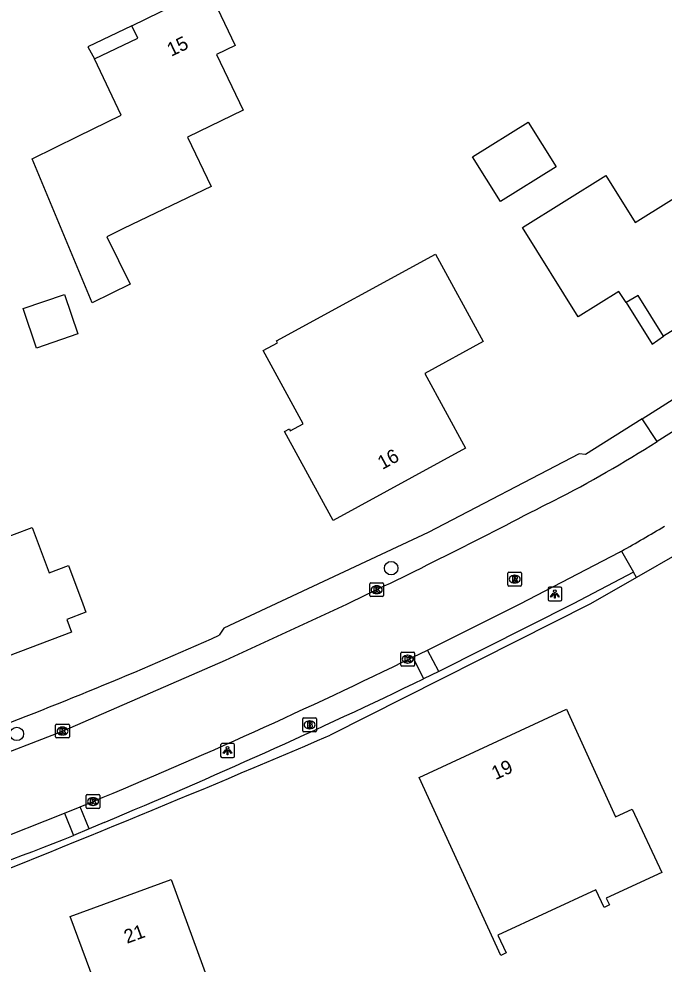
# Model space of a CAD drawing. Extents: x 162675 to 163482, y 379761 to 381227.
# Drawn here: x 163252.7 to 163299.4, y 380723.9 to 380792.3 of the extents above; entities that cross this region are included whole.
import ezdxf

# ---------------------------------------------------------------- set-up
doc = ezdxf.new("R2010")
doc.units = 0
for name, color, linetype in [('IMGEO_Boom', 7, 'Continuous'), ('IMGEO_Brandkraan', 7, 'Continuous'), ('IMGEO_Groenvoorziening', 7, 'Continuous'), ('IMGEO_Haag', 7, 'Continuous'), ('IMGEO_Kolk', 7, 'Continuous'), ('IMGEO_Lichtpunt', 7, 'Continuous'), ('IMGEO_Pand', 7, 'Continuous'), ('IMGEO_Pand_nummerreeks', 7, 'Continuous'), ('IMGEO_Pand_overbouw', 7, 'Continuous'), ('IMGEO_Parkeervlak_halfverhard', 7, 'Continuous'), ('IMGEO_Rijbaan_lokaal_gesloten', 7, 'Continuous'), ('IMGEO_Rioolput', 7, 'Continuous'), ('IMGEO_Voetpad_open', 7, 'Continuous')]:
    doc.layers.add(name, color=color, linetype=linetype)

msp = doc.modelspace()

# ---------------------------------------------------------------- linework, layer by layer
at = {"layer": 'IMGEO_Boom'}
for centre in [(163279.664, 380752.573), (163252.554, 380740.575)]:
    msp.add_circle(centre, 0.489, dxfattribs=at)
at = {"layer": 'IMGEO_Brandkraan'}
for p, q in [((163273.253, 380740.806), (163273.253, 380741.658)), ((163273.328, 380741.732), (163274.18, 380741.732)), ((163273.741, 380741.512), (163273.766, 380741.512)), ((163274.254, 380741.658), (163274.254, 380740.806)), ((163274.18, 380740.732), (163273.328, 380740.732)), ((163273.764, 380740.952), (163273.739, 380740.952))]:
    msp.add_line(p, q, dxfattribs=at)
for points in [[(163273.253, 380740.806), (163273.253, 380741.658)], [(163273.328, 380741.732), (163274.18, 380741.732)], [(163273.601, 380741.432), (163273.601, 380741.032), (163273.814, 380741.032)], [(163273.832, 380741.432), (163273.601, 380741.432)], [(163273.78, 380741.351), (163273.726, 380741.351), (163273.726, 380741.275)], [(163273.726, 380741.275), (163273.779, 380741.275)], [(163273.788, 380741.199), (163273.726, 380741.199), (163273.726, 380741.118)], [(163273.726, 380741.118), (163273.788, 380741.118)], [(163274.254, 380741.658), (163274.254, 380740.806)], [(163274.18, 380740.732), (163273.328, 380740.732)]]:
    msp.add_lwpolyline(points, dxfattribs=at)
for centre, radius, start, end in [((163273.33, 380741.656), 0.0765, 91.55205, 178.44795), ((163273.33, 380741.656), 0.0765, 91.55205, 178.44795), ((163273.781, 380741.313), 0.0379, 267.82845, 90.93552), ((163273.789, 380741.158), 0.0404, 269.87594, 90.50774), ((163273.836, 380741.287), 0.145, 59.4692, 91.53667), ((163273.861, 380741.334), 0.0922, 285.51372, 58.15012), ((163273.866, 380741.142), 0.105, 301.31148, 78.98903), ((163274.178, 380741.656), 0.0765, 1.55205, 88.44795), ((163274.178, 380741.656), 0.0765, 1.55205, 88.44795), ((163273.33, 380740.808), 0.0765, 181.55205, 268.44795), ((163273.33, 380740.808), 0.0765, 181.55205, 268.44795), ((163273.82, 380741.283), 0.251, 268.66757, 293.53466), ((163274.178, 380740.808), 0.0765, 271.55205, 358.44795), ((163274.178, 380740.808), 0.0765, 271.55205, 358.44795)]:
    msp.add_arc(centre, radius, start, end, dxfattribs=at)
for centre, major_axis, ratio, start_param, end_param in [((163273.74, 380741.232), (-0.387, 0.002), 0.722429, 4.712389, 7.853982), ((163273.765, 380741.232), (-0.39, 0.002), 0.717154, 1.570796, 4.712389)]:
    msp.add_ellipse(centre, major_axis=major_axis, ratio=ratio, start_param=start_param, end_param=end_param, dxfattribs=at)
at = {"layer": 'IMGEO_Groenvoorziening'}
msp.add_lwpolyline([(163297.826, 380763.387), (163293.739, 380760.802), (163293.264, 380760.865), (163282.331, 380755.165), (163267.534, 380748.225), (163267.198, 380747.716)], dxfattribs=at)
msp.add_arc((163142.434, 381025.573), 304.582, 290.53659, 294.1812, dxfattribs=at)
at = {"layer": 'IMGEO_Haag'}
msp.add_lwpolyline([(163297.434, 380751.907), (163294.098, 380750), (163275.249, 380740.479)], dxfattribs=at)
msp.add_arc((162843.961, 381747.352), 1095.355, 291.514053, 293.187575, dxfattribs=at)
at = {"layer": 'IMGEO_Kolk'}
for p, q in [((163278.11, 380750.589), (163278.11, 380751.441)), ((163278.185, 380751.515), (163279.037, 380751.515)), ((163279.111, 380751.441), (163279.111, 380750.589)), ((163278.621, 380750.735), (163278.596, 380750.735)), ((163278.598, 380751.295), (163278.623, 380751.295)), ((163279.037, 380750.515), (163278.185, 380750.515)), ((163280.36, 380745.559), (163280.36, 380746.411)), ((163280.435, 380746.485), (163281.287, 380746.485)), ((163280.848, 380746.265), (163280.873, 380746.265)), ((163281.361, 380746.411), (163281.361, 380745.559)), ((163281.287, 380745.485), (163280.435, 380745.485)), ((163280.871, 380745.705), (163280.846, 380745.705)), ((163255.363, 380740.356), (163255.363, 380741.208)), ((163255.438, 380741.282), (163256.29, 380741.282)), ((163256.364, 380741.208), (163256.364, 380740.356)), ((163255.874, 380740.502), (163255.849, 380740.502)), ((163255.851, 380741.062), (163255.876, 380741.062)), ((163256.29, 380740.282), (163255.438, 380740.282)), ((163257.572, 380735.251), (163257.572, 380736.103)), ((163257.647, 380736.177), (163258.499, 380736.177)), ((163258.06, 380735.957), (163258.085, 380735.957)), ((163258.573, 380736.103), (163258.573, 380735.251)), ((163258.499, 380735.177), (163257.647, 380735.177)), ((163258.083, 380735.397), (163258.058, 380735.397))]:
    msp.add_line(p, q, dxfattribs=at)
for points in [[(163278.11, 380750.589), (163278.11, 380751.441)], [(163278.185, 380751.515), (163279.037, 380751.515)], [(163279.111, 380751.441), (163279.111, 380750.589)], [(163278.431, 380751.215), (163278.554, 380751.215), (163278.554, 380751.064), (163278.684, 380751.215), (163278.848, 380751.215), (163278.702, 380751.064), (163278.855, 380750.815), (163278.703, 380750.815), (163278.618, 380750.979), (163278.554, 380750.912), (163278.554, 380750.815), (163278.431, 380750.815), (163278.431, 380751.215)], [(163279.037, 380750.515), (163278.185, 380750.515)], [(163280.36, 380745.559), (163280.36, 380746.411)], [(163280.435, 380746.485), (163281.287, 380746.485)], [(163280.681, 380746.185), (163280.804, 380746.185), (163280.804, 380746.034), (163280.934, 380746.185), (163281.098, 380746.185), (163280.952, 380746.034), (163281.105, 380745.785), (163280.953, 380745.785), (163280.868, 380745.949), (163280.804, 380745.882), (163280.804, 380745.785), (163280.681, 380745.785), (163280.681, 380746.185)], [(163281.361, 380746.411), (163281.361, 380745.559)], [(163281.287, 380745.485), (163280.435, 380745.485)], [(163255.363, 380740.356), (163255.363, 380741.208)], [(163255.438, 380741.282), (163256.29, 380741.282)], [(163256.364, 380741.208), (163256.364, 380740.356)], [(163255.684, 380740.982), (163255.807, 380740.982), (163255.807, 380740.831), (163255.937, 380740.982), (163256.101, 380740.982), (163255.955, 380740.831), (163256.108, 380740.582), (163255.956, 380740.582), (163255.871, 380740.746), (163255.807, 380740.679), (163255.807, 380740.582), (163255.684, 380740.582), (163255.684, 380740.982)], [(163256.29, 380740.282), (163255.438, 380740.282)], [(163257.572, 380735.251), (163257.572, 380736.103)], [(163257.647, 380736.177), (163258.499, 380736.177)], [(163257.893, 380735.877), (163258.016, 380735.877), (163258.016, 380735.726), (163258.146, 380735.877), (163258.31, 380735.877), (163258.164, 380735.726), (163258.317, 380735.477), (163258.165, 380735.477), (163258.08, 380735.641), (163258.016, 380735.574), (163258.016, 380735.477), (163257.893, 380735.477), (163257.893, 380735.877)], [(163258.573, 380736.103), (163258.573, 380735.251)], [(163258.499, 380735.177), (163257.647, 380735.177)]]:
    msp.add_lwpolyline(points, dxfattribs=at)
for centre, start, end in [((163278.187, 380751.439), 91.55205, 178.44795), ((163278.187, 380751.439), 91.55205, 178.44795), ((163279.035, 380751.439), 1.55205, 88.44795), ((163279.035, 380751.439), 1.55205, 88.44795), ((163278.187, 380750.591), 181.55205, 268.44795), ((163278.187, 380750.591), 181.55205, 268.44795), ((163279.035, 380750.591), 271.55205, 358.44795), ((163279.035, 380750.591), 271.55205, 358.44795), ((163280.437, 380746.409), 91.55205, 178.44795), ((163280.437, 380746.409), 91.55205, 178.44795), ((163281.285, 380746.409), 1.55205, 88.44795), ((163281.285, 380746.409), 1.55205, 88.44795), ((163280.437, 380745.561), 181.55205, 268.44795), ((163280.437, 380745.561), 181.55205, 268.44795), ((163281.285, 380745.561), 271.55205, 358.44795), ((163281.285, 380745.561), 271.55205, 358.44795), ((163255.44, 380741.206), 91.55205, 178.44795), ((163255.44, 380741.206), 91.55205, 178.44795), ((163256.288, 380741.206), 1.55205, 88.44795), ((163256.288, 380741.206), 1.55205, 88.44795), ((163255.44, 380740.358), 181.55205, 268.44795), ((163255.44, 380740.358), 181.55205, 268.44795), ((163256.288, 380740.358), 271.55205, 358.44795), ((163256.288, 380740.358), 271.55205, 358.44795), ((163257.649, 380736.101), 91.55205, 178.44795), ((163257.649, 380736.101), 91.55205, 178.44795), ((163258.497, 380736.101), 1.55205, 88.44795), ((163258.497, 380736.101), 1.55205, 88.44795), ((163257.649, 380735.253), 181.55205, 268.44795), ((163257.649, 380735.253), 181.55205, 268.44795), ((163258.497, 380735.253), 271.55205, 358.44795), ((163258.497, 380735.253), 271.55205, 358.44795)]:
    msp.add_arc(centre, 0.0765, start, end, dxfattribs=at)
for centre, major_axis, ratio, start_param, end_param in [((163278.597, 380751.015), (-0.387, 0.002), 0.722429, 4.712389, 7.853982), ((163278.622, 380751.015), (-0.39, 0.002), 0.717154, 1.570796, 4.712389), ((163280.847, 380745.985), (-0.387, 0.002), 0.722429, 4.712389, 7.853982), ((163280.872, 380745.985), (-0.39, 0.002), 0.717154, 1.570796, 4.712389), ((163255.85, 380740.782), (-0.387, 0.002), 0.722429, 4.712389, 7.853982), ((163255.875, 380740.782), (-0.39, 0.002), 0.717154, 1.570796, 4.712389), ((163258.059, 380735.677), (-0.387, 0.002), 0.722429, 4.712389, 7.853982), ((163258.084, 380735.677), (-0.39, 0.002), 0.717154, 1.570796, 4.712389)]:
    msp.add_ellipse(centre, major_axis=major_axis, ratio=ratio, start_param=start_param, end_param=end_param, dxfattribs=at)
at = {"layer": 'IMGEO_Lichtpunt'}
for p, q in [((163291.021, 380751.103), (163291.021, 380750.296)), ((163291.021, 380751.103), (163291.021, 380750.296)), ((163291.923, 380751.198), (163291.115, 380751.198)), ((163291.923, 380751.198), (163291.115, 380751.198)), ((163292.017, 380750.296), (163292.017, 380751.103)), ((163292.017, 380750.296), (163292.017, 380751.103)), ((163291.115, 380750.202), (163291.923, 380750.202)), ((163291.115, 380750.202), (163291.923, 380750.202)), ((163267.313, 380739.775), (163267.313, 380738.968)), ((163267.313, 380739.775), (163267.313, 380738.968)), ((163268.215, 380739.87), (163267.407, 380739.87)), ((163268.215, 380739.87), (163267.407, 380739.87)), ((163268.309, 380738.968), (163268.309, 380739.775)), ((163268.309, 380738.968), (163268.309, 380739.775)), ((163267.407, 380738.874), (163268.215, 380738.874)), ((163267.407, 380738.874), (163268.215, 380738.874))]:
    msp.add_line(p, q, dxfattribs=at)
for points in [[(163291.395, 380750.767), (163291.434, 380750.739), (163291.246, 380750.477), (163291.208, 380750.504), (163291.395, 380750.767)], [(163291.497, 380750.719), (163291.544, 380750.719), (163291.544, 380750.397), (163291.497, 380750.397), (163291.497, 380750.719)], [(163291.607, 380750.739), (163291.645, 380750.766), (163291.832, 380750.504), (163291.793, 380750.476), (163291.607, 380750.739)], [(163267.687, 380739.439), (163267.726, 380739.411), (163267.538, 380739.149), (163267.5, 380739.176), (163267.687, 380739.439)], [(163267.789, 380739.391), (163267.836, 380739.391), (163267.836, 380739.069), (163267.789, 380739.069), (163267.789, 380739.391)], [(163267.899, 380739.411), (163267.937, 380739.438), (163268.124, 380739.176), (163268.085, 380739.148), (163267.899, 380739.411)]]:
    msp.add_lwpolyline(points, dxfattribs=at)
for centre in [(163291.52, 380750.901), (163267.812, 380739.573)]:
    msp.add_circle(centre, 0.0994, dxfattribs=at)
for centre, start, end in [((163291.115, 380751.103), 90, 180), ((163291.115, 380751.103), 90, 180), ((163291.923, 380751.103), 0, 90), ((163291.923, 380751.103), 0, 90), ((163291.115, 380750.296), 180, 270), ((163291.115, 380750.296), 180, 270), ((163291.923, 380750.296), 270, 0), ((163291.923, 380750.296), 270, 360), ((163267.407, 380739.775), 90, 180), ((163267.407, 380739.775), 90, 180), ((163268.215, 380739.775), 0, 90), ((163268.215, 380739.775), 0, 90), ((163267.407, 380738.968), 180, 270), ((163267.407, 380738.968), 180, 270), ((163268.215, 380738.968), 270, 0), ((163268.215, 380738.968), 270, 360)]:
    msp.add_arc(centre, 0.0946, start, end, dxfattribs=at)
at = {"layer": 'IMGEO_Pand'}
for points in [[(163253.665, 380782.214), (163257, 380783.85), (163260.107, 380785.374), (163258.187, 380789.453), (163261.323, 380790.949), (163260.87, 380791.844), (163265.036, 380793.887), (163265.476, 380792.989), (163266.81, 380793.645), (163268.36, 380790.421), (163267.007, 380789.77), (163268.949, 380785.731), (163264.911, 380783.788), (163266.628, 380780.215), (163260.28, 380777.161), (163259.079, 380776.572), (163260.761, 380773.143), (163258.014, 380771.796), (163253.665, 380782.214)], [(163285.557, 380782.368), (163289.592, 380784.881), (163291.609, 380781.643), (163287.574, 380779.129), (163285.557, 380782.368)], [(163289.175, 380777.245), (163295.205, 380781.001), (163297.324, 380777.599), (163302.002, 380780.514), (163303.856, 380777.537), (163305.141, 380778.338), (163307.043, 380775.29), (163305.753, 380774.487), (163306.278, 380773.636), (163299.39, 380769.368), (163297.548, 380772.324), (163296.676, 380771.801), (163296.157, 380772.609), (163293.2, 380770.781), (163289.175, 380777.245)], [(163282.861, 380775.314), (163286.321, 380768.98), (163282.103, 380766.676), (163285.053, 380761.265), (163275.465, 380756.033), (163271.945, 380762.47), (163272.287, 380762.657), (163272.357, 380762.53), (163273.283, 380763.037), (163270.402, 380768.339), (163271.43, 380768.898), (163271.361, 380769.025), (163282.861, 380775.314)], [(163253.009, 380771.377), (163255.995, 380772.4), (163256.976, 380769.535), (163253.99, 380768.512), (163253.009, 380771.377)], [(163247.112, 380757.329), (163248.511, 380753.586), (163253.659, 380755.51), (163254.884, 380752.235), (163256.298, 380752.763), (163257.331, 380750), (163257.558, 380749.394), (163256.169, 380748.87), (163256.521, 380747.934), (163248.914, 380745.076), (163247.693, 380748.359), (163246.755, 380748.011), (163246.407, 380748.945), (163243.125, 380747.725), (163242.279, 380750), (163240.475, 380754.848), (163247.112, 380757.329)], [(163281.699, 380737.414), (163292.362, 380742.364), (163295.911, 380734.575), (163297.118, 380735.135), (163299.25, 380730.546), (163295.236, 380728.681), (163295.463, 380728.191), (163295.082, 380728.014), (163294.488, 380729.293), (163287.387, 380725.994), (163287.981, 380724.715), (163287.601, 380724.538), (163281.699, 380737.414)], [(163258.147, 380722.668), (163256.427, 380727.362), (163263.72, 380730.034), (163266.82, 380721.574), (163266.472, 380721.447), (163266.665, 380720.921), (163269.548, 380721.977), (163271.481, 380716.7), (163271.19, 380716.593), (163270.887, 380717.42), (163263.376, 380714.667), (163263.678, 380713.841), (163263.387, 380713.735), (163261.45, 380719.021), (163261.685, 380719.107), (163261.488, 380719.644), (163259.519, 380718.923), (163258.147, 380722.668)]]:
    msp.add_lwpolyline(points, dxfattribs=at)
at = {"layer": 'IMGEO_Pand_overbouw'}
for points in [[(163260.87, 380791.844), (163257.707, 380790.32), (163258.187, 380789.453), (163261.323, 380790.949)], [(163299.39, 380769.368), (163297.548, 380772.324), (163296.676, 380771.801), (163298.556, 380768.795)]]:
    msp.add_lwpolyline(points, close=True, dxfattribs=at)
at = {"layer": 'IMGEO_Parkeervlak_halfverhard'}
for points in [[(163297.211, 380752.298), (163292.832, 380750), (163283.121, 380745.094)], [(163258.886, 380734.167), (163257.799, 380733.693)]]:
    msp.add_lwpolyline(points, dxfattribs=at)
for centre, radius, start, end in [((163072.398, 381179.996), 483.261, 292.69928, 295.7053), ((163151.239, 380997.533), 284.555, 289.18805, 291.74558)]:
    msp.add_arc(centre, radius, start, end, dxfattribs=at)
at = {"layer": 'IMGEO_Rijbaan_lokaal_gesloten'}
for points in [[(163302.043, 380763.7), (163298.915, 380761.754)], [(163290.612, 380757.064), (163291.457, 380757.471)], [(163282.299, 380746.646), (163289.013, 380750), (163296.201, 380753.731), (163296.274, 380753.772), (163296.346, 380753.813)], [(163249.96, 380738.497), (163255.863, 380740.782), (163267.666, 380745.904), (163276.451, 380749.977), (163276.5, 380750)], [(163281.232, 380746.134), (163282.299, 380746.646)], [(163257.152, 380735.296), (163258.073, 380735.677)], [(163255.996, 380734.84), (163257.152, 380735.296)], [(163244.16, 380730.415), (163250.508, 380732.673), (163255.996, 380734.84)]]:
    msp.add_lwpolyline(points, dxfattribs=at)
for centre, radius, start, end in [((163251.098, 380836.383), 88.634, 297.08714, 302.64887), ((163092.411, 381135.388), 427.098, 295.53243, 297.64963), ((163168.961, 380978.153), 257.984, 299.58877, 300.38726), ((163100.068, 381116.482), 412.283, 292.53469, 296.06658)]:
    msp.add_arc(centre, radius, start, end, dxfattribs=at)
at = {"layer": 'IMGEO_Rioolput'}
for p, q in [((163288.107, 380751.357), (163288.107, 380752.209)), ((163288.182, 380752.283), (163289.034, 380752.283)), ((163289.108, 380752.209), (163289.108, 380751.357)), ((163288.618, 380751.503), (163288.593, 380751.503)), ((163288.595, 380752.063), (163288.62, 380752.063)), ((163289.034, 380751.283), (163288.182, 380751.283))]:
    msp.add_line(p, q, dxfattribs=at)
for points in [[(163288.107, 380751.357), (163288.107, 380752.209)], [(163288.182, 380752.283), (163289.034, 380752.283)], [(163289.108, 380752.209), (163289.108, 380751.357)], [(163288.696, 380751.981), (163288.444, 380751.983), (163288.444, 380751.583)], [(163288.444, 380751.583), (163288.568, 380751.583), (163288.568, 380751.745), (163288.579, 380751.745)], [(163288.622, 380751.902), (163288.568, 380751.902), (163288.568, 380751.821)], [(163288.568, 380751.821), (163288.62, 380751.821)], [(163288.626, 380751.716), (163288.697, 380751.583), (163288.837, 380751.583), (163288.772, 380751.709)], [(163289.034, 380751.283), (163288.182, 380751.283)]]:
    msp.add_lwpolyline(points, dxfattribs=at)
for centre, radius, start, end in [((163288.184, 380752.207), 0.0765, 91.55205, 178.44795), ((163288.184, 380752.207), 0.0765, 91.55205, 178.44795), ((163289.032, 380752.207), 0.0765, 1.55205, 88.44795), ((163289.032, 380752.207), 0.0765, 1.55205, 88.44795), ((163288.578, 380751.692), 0.0533, 26.02933, 88.69889), ((163288.604, 380752.01), 0.19, 274.7715, 282.96867), ((163288.628, 380751.806), 0.0964, 77.00612, 93.18647), ((163288.642, 380751.863), 0.0378, 276.66336, 79.67722), ((163288.695, 380751.871), 0.109, 350.36119, 89.41601), ((163288.693, 380751.871), 0.112, 277.58423, 350.98172), ((163288.677, 380751.656), 0.108, 29.51342, 73.79051), ((163288.184, 380751.359), 0.0765, 181.55205, 268.44795), ((163288.184, 380751.359), 0.0765, 181.55205, 268.44795), ((163289.032, 380751.359), 0.0765, 271.55205, 358.44795), ((163289.032, 380751.359), 0.0765, 271.55205, 358.44795)]:
    msp.add_arc(centre, radius, start, end, dxfattribs=at)
for centre, major_axis, ratio, start_param, end_param in [((163288.594, 380751.783), (-0.387, 0.002), 0.722429, 4.712389, 7.853982), ((163288.619, 380751.783), (-0.39, 0.002), 0.717154, 1.570796, 4.712389)]:
    msp.add_ellipse(centre, major_axis=major_axis, ratio=ratio, start_param=start_param, end_param=end_param, dxfattribs=at)
at = {"layer": 'IMGEO_Voetpad_open'}
for points in [[(163297.826, 380763.387), (163300.998, 380765.394)], [(163298.915, 380761.754), (163297.826, 380763.387)], [(163296.346, 380753.813), (163297.211, 380752.298)], [(163300.552, 380753.691), (163297.434, 380751.907)], [(163297.434, 380751.907), (163297.211, 380752.298)], [(163283.121, 380745.094), (163282.299, 380746.646)], [(163281.232, 380746.134), (163282.009, 380744.56)], [(163283.121, 380745.094), (163282.009, 380744.56)], [(163257.799, 380733.693), (163257.152, 380735.296)], [(163255.996, 380734.84), (163256.662, 380733.228)], [(163257.799, 380733.693), (163256.662, 380733.228)]]:
    msp.add_lwpolyline(points, dxfattribs=at)

# ---------------------------------------------------------------- texts
at = {"layer": 'IMGEO_Pand_nummerreeks'}
for s, rotation, p in [('15', 26.12688, (163263.737, 380789.597)), ('16', 28.61924, (163279.024, 380759.684)), ('19', 24.90075, (163287.218, 380737.22)), ('21', 20.12176, (163260.532, 380725.373))]:
    msp.add_text(s, height=1, rotation=rotation, dxfattribs=at).set_placement(p)

doc.saveas('drawing.dxf')
